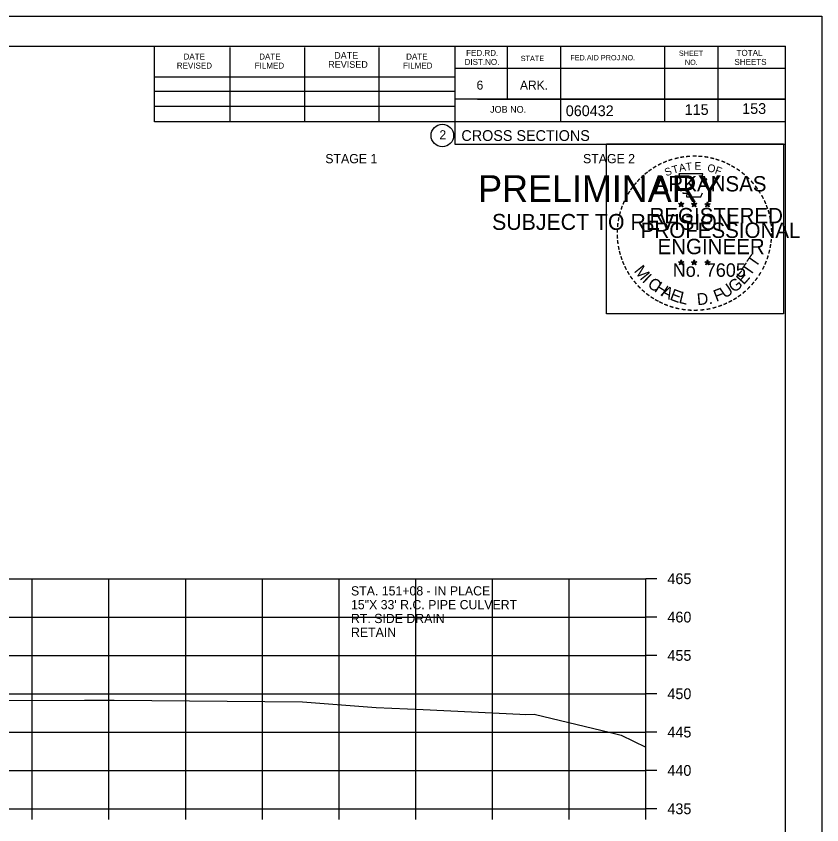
# Model space of a CAD drawing. Extents: x 1538688 to 1540766, y 656250 to 671912.
# Drawn here: x 1538916.1 to 1539021.1, y 664979.3 to 665084.8 of the extents above; entities that cross this region are included whole.
import ezdxf

# ---------------------------------------------------------------- set-up
doc = ezdxf.new("R2010")
doc.units = 0
for name, color, linetype in [('18', 7, 'Continuous'), ('22', 7, 'Continuous'), ('26', 7, 'Continuous'), ('7', 7, 'Continuous'), ('8', 7, 'Continuous'), ('9', 7, 'Continuous'), ('Borings', 7, 'Continuous'), ('Default', 7, 'Continuous'), ('Horizontal Alignment', 7, 'Continuous'), ('RipRap', 7, 'Continuous')]:
    doc.layers.add(name, color=color, linetype=linetype)

msp = doc.modelspace()

# ---------------------------------------------------------------- linework, layer by layer
at = {"layer": '18'}
msp.add_lwpolyline([(1538910.99, 664995.54), (1538924.98, 664995.57), (1538927.5, 664995.56), (1538928.54, 664995.55), (1538928.86, 664995.55), (1538953.39, 664995.37), (1538962.99, 664994.59), (1538969.15, 664994.37), (1538981.75, 664993.74), (1538982.53, 664993.71), (1538983.63, 664993.72), (1538993.58, 664991.37), (1538994.96, 664991.02), (1538998.18, 664989.45)], dxfattribs=at)
at = {"layer": '22'}
for p, q in [((1538718.18, 665011.4), (1538998.18, 665011.4)), ((1538918.18, 664981.4), (1538918.18, 665011.4)), ((1538928.18, 664981.4), (1538928.18, 665011.4)), ((1538938.18, 664981.4), (1538938.18, 665011.4)), ((1538948.18, 664981.4), (1538948.18, 665011.4)), ((1538958.18, 664981.4), (1538958.18, 665011.4)), ((1538968.18, 664981.4), (1538968.18, 665011.4)), ((1538978.18, 664981.4), (1538978.18, 665011.4)), ((1538988.18, 664981.4), (1538988.18, 665011.4)), ((1538998.18, 664981.4), (1538998.18, 665011.4)), ((1538718.18, 665006.4), (1538998.18, 665006.4)), ((1538718.18, 665001.4), (1538998.18, 665001.4)), ((1538718.18, 664996.4), (1538998.18, 664996.4)), ((1538718.18, 664991.4), (1538998.18, 664991.4)), ((1538718.18, 664986.4), (1538998.18, 664986.4)), ((1538718.18, 664981.4), (1538998.18, 664981.4))]:
    msp.add_line(p, q, dxfattribs=at)
at = {"layer": '26'}
msp.add_line((1538687.78, 665084.75), (1539021.11, 665084.75), dxfattribs=at)
for points in [[(1538687.77, 665084.75), (1539021.11, 665084.75), (1539021.11, 664871.42), (1538687.77, 664871.42)], [(1538993.03, 665068.09), (1539016.13, 665068.09), (1539016.13, 665045.94), (1538993.03, 665045.94)]]:
    msp.add_lwpolyline(points, close=True, dxfattribs=at)
at = {"layer": '8'}
for p, q in [((1539002.44, 665060.31), (1539002.79, 665060.2)), ((1539002.44, 665060.31), (1539002.69, 665060.26)), ((1539002.44, 665060.31), (1539002.68, 665060.18)), ((1539002.57, 665059.9), (1539002.79, 665060.2)), ((1539002.57, 665059.9), (1539002.7, 665060.14)), ((1539002.57, 665059.9), (1539002.79, 665060.12)), ((1539002.79, 665060.56), (1539002.75, 665060.31)), ((1539002.79, 665060.2), (1539002.79, 665060.56)), ((1539002.79, 665060.56), (1539002.84, 665060.31)), ((1539003.13, 665060.31), (1539002.79, 665060.2)), ((1539003, 665059.9), (1539002.79, 665060.2)), ((1539003, 665059.9), (1539002.79, 665060.11)), ((1539003.13, 665060.31), (1539002.85, 665060.26)), ((1539003, 665059.9), (1539002.86, 665060.19)), ((1539003.13, 665060.31), (1539002.93, 665060.2)), ((1539004.11, 665060.31), (1539004.46, 665060.2)), ((1539004.11, 665060.31), (1539004.36, 665060.26)), ((1539004.11, 665060.31), (1539004.35, 665060.18)), ((1539004.24, 665059.9), (1539004.46, 665060.2)), ((1539004.24, 665059.9), (1539004.37, 665060.14)), ((1539004.24, 665059.9), (1539004.46, 665060.12)), ((1539004.46, 665060.56), (1539004.42, 665060.31)), ((1539004.46, 665060.2), (1539004.46, 665060.56)), ((1539004.46, 665060.56), (1539004.51, 665060.31)), ((1539004.8, 665060.31), (1539004.46, 665060.2)), ((1539004.67, 665059.9), (1539004.46, 665060.2)), ((1539004.67, 665059.9), (1539004.46, 665060.11)), ((1539004.8, 665060.31), (1539004.52, 665060.26)), ((1539004.67, 665059.9), (1539004.53, 665060.19)), ((1539004.8, 665060.31), (1539004.6, 665060.2)), ((1539005.87, 665060.29), (1539006.22, 665060.18)), ((1539005.87, 665060.29), (1539006.13, 665060.25)), ((1539005.87, 665060.29), (1539006.11, 665060.17)), ((1539006.01, 665059.89), (1539006.22, 665060.18)), ((1539006.01, 665059.89), (1539006.13, 665060.13)), ((1539006.01, 665059.89), (1539006.22, 665060.1)), ((1539006.22, 665060.55), (1539006.18, 665060.3)), ((1539006.22, 665060.18), (1539006.22, 665060.55)), ((1539006.22, 665060.55), (1539006.27, 665060.3)), ((1539006.57, 665060.29), (1539006.22, 665060.18)), ((1539006.43, 665059.89), (1539006.22, 665060.18)), ((1539006.43, 665059.89), (1539006.22, 665060.1)), ((1539006.57, 665060.29), (1539006.28, 665060.25)), ((1539006.43, 665059.89), (1539006.3, 665060.18)), ((1539006.57, 665060.29), (1539006.36, 665060.19)), ((1539002.43, 665052.73), (1539002.78, 665052.62)), ((1539002.43, 665052.73), (1539002.69, 665052.69)), ((1539002.43, 665052.73), (1539002.67, 665052.61)), ((1539002.57, 665052.33), (1539002.78, 665052.62)), ((1539002.57, 665052.33), (1539002.69, 665052.57)), ((1539002.78, 665052.99), (1539002.74, 665052.74)), ((1539002.78, 665052.62), (1539002.78, 665052.99)), ((1539002.78, 665052.99), (1539002.83, 665052.74)), ((1539003.13, 665052.73), (1539002.78, 665052.62)), ((1539003, 665052.33), (1539002.78, 665052.62)), ((1539003.13, 665052.73), (1539002.84, 665052.68)), ((1539003, 665052.33), (1539002.86, 665052.62)), ((1539003.13, 665052.73), (1539002.93, 665052.63)), ((1539004.1, 665052.73), (1539004.45, 665052.62)), ((1539004.1, 665052.73), (1539004.36, 665052.69)), ((1539004.1, 665052.73), (1539004.34, 665052.61)), ((1539004.24, 665052.33), (1539004.45, 665052.62)), ((1539004.24, 665052.33), (1539004.36, 665052.57)), ((1539004.45, 665052.99), (1539004.41, 665052.74)), ((1539004.45, 665052.62), (1539004.45, 665052.99)), ((1539004.45, 665052.99), (1539004.5, 665052.74)), ((1539004.8, 665052.73), (1539004.45, 665052.62)), ((1539004.67, 665052.33), (1539004.45, 665052.62)), ((1539004.8, 665052.73), (1539004.51, 665052.68)), ((1539004.67, 665052.33), (1539004.53, 665052.62)), ((1539004.8, 665052.73), (1539004.6, 665052.63)), ((1539005.87, 665052.72), (1539006.22, 665052.61)), ((1539005.87, 665052.72), (1539006.12, 665052.68)), ((1539005.87, 665052.72), (1539006.11, 665052.6)), ((1539006, 665052.32), (1539006.22, 665052.61)), ((1539006, 665052.32), (1539006.13, 665052.56)), ((1539006.22, 665052.98), (1539006.18, 665052.73)), ((1539006.22, 665052.61), (1539006.22, 665052.98)), ((1539006.22, 665052.98), (1539006.27, 665052.73)), ((1539006.57, 665052.72), (1539006.22, 665052.61)), ((1539006.43, 665052.32), (1539006.22, 665052.61)), ((1539006.57, 665052.72), (1539006.28, 665052.67)), ((1539006.43, 665052.32), (1539006.3, 665052.61)), ((1539006.57, 665052.72), (1539006.36, 665052.62)), ((1539002.57, 665052.33), (1539002.78, 665052.54)), ((1539003, 665052.33), (1539002.78, 665052.54)), ((1539004.24, 665052.33), (1539004.45, 665052.54)), ((1539004.67, 665052.33), (1539004.45, 665052.54)), ((1539006, 665052.32), (1539006.22, 665052.53)), ((1539006.43, 665052.32), (1539006.22, 665052.53))]:
    msp.add_line(p, q, dxfattribs=at)
for points in [[(1539002.48, 665064.18), (1539002.75, 665063.36)], [(1539005.99, 665063.26), (1539006.13, 665063.55), (1539005.45, 665063.52), (1539005.6, 665064.18), (1539002.48, 665064.18)], [(1539002.97, 665061.76), (1539002.97, 665061.67), (1539003.53, 665061.66), (1539003.48, 665061.18), (1539005.35, 665061.18), (1539005.55, 665061.72)], [(1539002.79, 665060.56), (1539003, 665059.9), (1539002.44, 665060.31), (1539003.13, 665060.31), (1539002.57, 665059.9), (1539002.79, 665060.56)], [(1539004.46, 665060.56), (1539004.67, 665059.9), (1539004.11, 665060.31), (1539004.8, 665060.31), (1539004.24, 665059.9), (1539004.46, 665060.56)], [(1539006.22, 665060.55), (1539006.43, 665059.89), (1539005.87, 665060.29), (1539006.57, 665060.29), (1539006.01, 665059.89), (1539006.22, 665060.55)], [(1539002.78, 665052.99), (1539003, 665052.33), (1539002.43, 665052.73), (1539003.13, 665052.73), (1539002.57, 665052.33), (1539002.78, 665052.99)], [(1539004.45, 665052.99), (1539004.67, 665052.33), (1539004.1, 665052.73), (1539004.8, 665052.73), (1539004.24, 665052.33), (1539004.45, 665052.99)], [(1539006.22, 665052.98), (1539006.43, 665052.32), (1539005.87, 665052.72), (1539006.57, 665052.72), (1539006, 665052.32), (1539006.22, 665052.98)]]:
    msp.add_lwpolyline(points, dxfattribs=at)
for centre, radius in [((1539002.79, 665060.2), 0.172), ((1539002.79, 665060.2), 0.145), ((1539002.79, 665060.2), 0.116), ((1539002.79, 665060.2), 0.0991), ((1539002.79, 665060.2), 0.0747), ((1539002.79, 665060.2), 0.0495), ((1539002.79, 665060.2), 0.0296), ((1539004.46, 665060.2), 0.172), ((1539004.46, 665060.2), 0.145), ((1539004.46, 665060.2), 0.116), ((1539004.46, 665060.2), 0.0991), ((1539004.46, 665060.2), 0.0747), ((1539004.46, 665060.2), 0.0495), ((1539004.46, 665060.2), 0.0296), ((1539006.22, 665060.18), 0.172), ((1539006.22, 665060.18), 0.145), ((1539006.22, 665060.18), 0.116), ((1539006.22, 665060.18), 0.0991), ((1539006.22, 665060.18), 0.0747), ((1539006.22, 665060.18), 0.0495), ((1539006.22, 665060.18), 0.0296), ((1539002.78, 665052.62), 0.172), ((1539002.78, 665052.62), 0.145), ((1539002.78, 665052.62), 0.116), ((1539002.78, 665052.62), 0.0991), ((1539002.78, 665052.62), 0.0747), ((1539002.78, 665052.62), 0.0495), ((1539002.78, 665052.62), 0.0296), ((1539004.45, 665052.62), 0.172), ((1539004.45, 665052.62), 0.145), ((1539004.45, 665052.62), 0.116), ((1539004.45, 665052.62), 0.0991), ((1539004.45, 665052.62), 0.0747), ((1539004.45, 665052.62), 0.0495), ((1539004.45, 665052.62), 0.0296), ((1539006.22, 665052.61), 0.172), ((1539006.22, 665052.61), 0.145), ((1539006.22, 665052.61), 0.116), ((1539006.22, 665052.61), 0.0991), ((1539006.22, 665052.61), 0.0747), ((1539006.22, 665052.61), 0.0495), ((1539006.22, 665052.61), 0.0296)]:
    msp.add_circle(centre, radius, dxfattribs=at)
at = {"layer": 'Borings'}
for p, q in [((1538998.18, 664981.4), (1538998.18, 665011.4)), ((1538999.58, 665011.4), (1538998.18, 665011.4)), ((1538999.58, 665006.4), (1538998.18, 665006.4)), ((1538999.58, 665001.4), (1538998.18, 665001.4)), ((1538999.58, 664996.4), (1538998.18, 664996.4)), ((1538999.58, 664991.4), (1538998.18, 664991.4)), ((1538999.58, 664986.4), (1538998.18, 664986.4)), ((1538718.18, 664981.4), (1538998.18, 664981.4)), ((1538918.18, 664980), (1538918.18, 664981.4)), ((1538928.18, 664980), (1538928.18, 664981.4)), ((1538938.18, 664980), (1538938.18, 664981.4)), ((1538948.18, 664980), (1538948.18, 664981.4)), ((1538958.18, 664980), (1538958.18, 664981.4)), ((1538968.18, 664980), (1538968.18, 664981.4)), ((1538978.18, 664980), (1538978.18, 664981.4)), ((1538988.18, 664980), (1538988.18, 664981.4)), ((1538998.18, 664980), (1538998.18, 664981.4)), ((1538999.58, 664981.4), (1538998.18, 664981.4))]:
    msp.add_line(p, q, dxfattribs=at)
at = {"layer": 'RipRap'}
for p, q in [((1538700.18, 665080.86), (1539016.36, 665080.86)), ((1538934.1, 665070.98), (1538934.1, 665080.86)), ((1538943.96, 665070.98), (1538943.96, 665080.66)), ((1538953.72, 665070.98), (1538953.72, 665080.66)), ((1538963.4, 665070.98), (1538963.4, 665080.66)), ((1538973.26, 665080.86), (1538973.26, 665068.06)), ((1538980.1, 665080.86), (1538980.1, 665073.92)), ((1538987.04, 665080.86), (1538987.04, 665070.98)), ((1539000.62, 665080.86), (1539000.62, 665070.98)), ((1539007.56, 665080.86), (1539007.56, 665070.98)), ((1539016.36, 664875.4), (1539016.36, 665080.86)), ((1539016.36, 665077.92), (1538973.26, 665077.92)), ((1539016.36, 665077.94), (1539016.36, 665077.94)), ((1538934.1, 665076.84), (1538973.26, 665076.84)), ((1538934.1, 665074.98), (1538973.26, 665074.98)), ((1539016.36, 665073.92), (1538973.26, 665073.92)), ((1538976.22, 665073.92), (1539016.36, 665073.92)), ((1538934.1, 665070.98), (1538934.1, 665073.04)), ((1538934.1, 665073.04), (1538973.26, 665073.04)), ((1539016.36, 665070.98), (1538934.1, 665070.98)), ((1538973.26, 665068.06), (1539016.36, 665068.06))]:
    msp.add_line(p, q, dxfattribs=at)
msp.add_circle((1538971.64, 665069.2), 1.47, dxfattribs=at)

# ---------------------------------------------------------------- texts
at = {"layer": '7'}
for s, p in [('115', (1539003.23, 665071.88)), ('153', (1539010.73, 665072.01))]:
    msp.add_text(s, height=1.4, dxfattribs=at).set_placement(p)
at = {"layer": '8'}
for s, height, rotation, p in [('-', 1.6, 13.6301, (1539001.98, 665065.55)), ('-', 1.6, 10.2193, (1539002.66, 665065.71)), ('-', 1.6, 5.8968, (1539003.38, 665065.82)), ('-', 1.6, 0.1862, (1539004.16, 665065.9)), ('-', 1.6, 357.743, (1539004.88, 665065.88)), ('-', 1.6, 352.1617, (1539005.62, 665065.83)), ('-', 1.6, 347.2049, (1539006.34, 665065.71)), ('-', 1.6, 34.0636, (1538999.36, 665064.36)), ('-', 1.6, 28.7918, (1538999.96, 665064.73)), ('-', 1.6, 24.3072, (1539000.59, 665065.04)), ('-', 1.6, 19.1761, (1539001.23, 665065.31)), ('T', 1, 16.4036, (1539001.75, 665064.19)), ('A', 1, 11.2132, (1539002.57, 665064.44)), ('T', 1, 6.0228, (1539003.42, 665064.61)), ('E', 1, 0.8323, (1539004.53, 665064.72)), ('O', 1, 350.4515, (1539006.13, 665064.51)), ('-', 1.6, 342.3362, (1539006.98, 665065.56)), ('-', 1.6, 337.8551, (1539007.71, 665065.34)), ('-', 1.6, 334.1211, (1539008.34, 665065.06)), ('-', 1.6, 329.6409, (1539008.92, 665064.78)), ('-', 1.6, 38.9507, (1538998.31, 665063.58)), ('-', 1.6, 36.2317, (1538998.79, 665063.96)), ('S', 1, 21.594, (1539000.83, 665063.86)), ('F', 1, 340.0707, (1539007.09, 665064.28)), ('-', 1.6, 325.8627, (1539009.57, 665064.42)), ('-', 1.6, 320.5297, (1539010.18, 665063.99)), ('-', 1.6, 50.6142, (1538997.03, 665062.2)), ('-', 1.6, 48.423, (1538997.43, 665062.69)), ('-', 1.6, 42.9622, (1538997.88, 665063.17)), ('ARKANSAS', 2, 360, (1538999.33, 665061.9)), ('-', 1.6, 315.5786, (1539010.77, 665063.51)), ('-', 1.6, 309.8797, (1539011.34, 665062.96)), ('-', 1.6, 54.2325, (1538996.61, 665061.63)), ('-', 1.6, 306.6522, (1539011.87, 665062.35)), ('-', 1.4, 303.6753, (1539012.35, 665061.79)), ('-', 1.6, 62.8713, (1538995.97, 665060.49)), ('-', 1.6, 58.0706, (1538996.29, 665061.11)), ('-', 1.6, 299.6684, (1539012.67, 665061.18)), ('-', 1.6, 72.3945, (1538995.5, 665059.25)), ('-', 1.6, 67.7743, (1538995.72, 665059.88)), ('DWB', 0.01, 360, (1539002.77, 665060.19)), ('DWB', 0.01, 360, (1539004.44, 665060.19)), ('DWB', 0.01, 360, (1539006.21, 665060.18)), ('-', 1.6, 294.6628, (1539013, 665060.57)), ('-', 1.6, 290.5728, (1539013.25, 665059.99)), ('-', 1.6, 75.461, (1538995.3, 665058.54)), ('REGISTERED', 2, 360, (1538998.65, 665057.75)), ('-', 1.6, 285.1233, (1539013.49, 665059.41)), ('-', 1.6, 81.2013, (1538995.17, 665057.83)), ('PROFESSIONAL', 2, 360, (1538997.51, 665055.84)), ('-', 1.6, 280.5493, (1539013.69, 665058.67)), ('-', 1.6, 276.5962, (1539013.85, 665057.9)), ('-', 1.6, 89.0622, (1538995.07, 665056.43)), ('-', 1.6, 85.1863, (1538995.09, 665057.13)), ('-', 1.6, 274.3301, (1539013.91, 665057.18)), ('-', 1.6, 94.1959, (1538995.1, 665055.71)), ('ENGINEER', 2, 360, (1538999.69, 665053.72)), ('-', 1.6, 263.5172, (1539013.93, 665055.88)), ('-', 1.6, 269.9407, (1539013.94, 665056.55)), ('-', 1.6, 98.9479, (1538995.17, 665055.04)), ('-', 1.6, 101.7149, (1538995.31, 665054.31)), ('-', 1.6, 260.9953, (1539013.85, 665055.23)), ('-', 1.6, 105.4578, (1538995.47, 665053.71)), ('T', 1.54, 55.055, (1539012.5, 665051.89)), ('-', 1.6, 255.7626, (1539013.74, 665054.55)), ('-', 1.6, 109.0874, (1538995.69, 665053.08)), ('-', 1.6, 114.0643, (1538995.94, 665052.49)), ('No. 7605', 1.757, 360, (1539001.67, 665050.77)), ('DWB', 0.01, 360, (1539002.77, 665052.62)), ('DWB', 0.01, 360, (1539004.44, 665052.62)), ('DWB', 0.01, 360, (1539006.2, 665052.61)), ('T', 1.54, 55.055, (1539011.77, 665050.77)), ('-', 1.6, 247.8887, (1539013.34, 665053.16)), ('-', 1.6, 252.8681, (1539013.56, 665053.83)), ('-', 1.6, 115.7289, (1538996.24, 665051.87)), ('-', 1.6, 120.4471, (1538996.6, 665051.28)), ('M', 1.54, 308.9175, (1538996.55, 665051.51)), ('E', 1.54, 48.7313, (1539010.93, 665049.64)), ('-', 1.6, 244.6197, (1539013.08, 665052.53)), ('-', 1.6, 125.8934, (1538997, 665050.72)), ('I', 1.54, 316.4636, (1538997.6, 665050.19)), ('C', 1.54, 324.0197, (1538998.27, 665049.57)), ('G', 1.54, 38.2173, (1539009.67, 665048.62)), ('-', 1.6, 233.8452, (1539012.28, 665051.12)), ('-', 1.6, 239.0712, (1539012.68, 665051.77)), ('-', 1.6, 130.7181, (1538997.47, 665050.17)), ('-', 1.6, 134.2238, (1538997.98, 665049.62)), ('H', 1.54, 327.5342, (1538999.18, 665048.92)), ('A', 1.54, 332.5513, (1539000.03, 665048.38)), ('U', 1.54, 34.4052, (1539008.47, 665047.89)), ('-', 1.6, 225.7653, (1539011.37, 665049.99)), ('-', 1.6, 231.2538, (1539011.85, 665050.56)), ('-', 1.6, 138.9338, (1538998.51, 665049.16)), ('-', 1.6, 144.6463, (1538999.06, 665048.75)), ('E', 1.54, 339.2068, (1539001.19, 665047.82)), ('L', 1.54, 346.2929, (1539002.38, 665047.39)), ('D.', 1.54, 5.2602, (1539004.89, 665047.06)), ('F', 1.54, 20.8202, (1539007.34, 665047.49)), ('-', 1.6, 215.7363, (1539010.3, 665049.01)), ('-', 1.6, 221.0851, (1539010.85, 665049.48)), ('-', 1.6, 148.0898, (1538999.63, 665048.38)), ('-', 1.6, 151.5704, (1539000.2, 665048.06)), ('-', 1.6, 154.6002, (1539000.73, 665047.81)), ('-', 1.6, 158.5612, (1539001.35, 665047.56)), ('-', 1.6, 204.2516, (1539008.59, 665047.96)), ('-', 1.6, 207.3568, (1539009.21, 665048.28)), ('-', 1.6, 212.2491, (1539009.77, 665048.62)), ('-', 1.6, 162.7983, (1539002.04, 665047.34)), ('-', 1.6, 167.5555, (1539002.75, 665047.18)), ('-', 1.6, 173.1155, (1539003.52, 665047.07)), ('-', 1.6, 176.5183, (1539004.27, 665047.02)), ('-', 1.6, 181.5918, (1539005.02, 665047.04)), ('-', 1.6, 185.8167, (1539005.83, 665047.11)), ('-', 1.6, 191.2858, (1539006.56, 665047.24)), ('-', 1.6, 195.4743, (1539007.29, 665047.44)), ('-', 1.6, 200.7184, (1539007.97, 665047.69))]:
    msp.add_text(s, height=height, rotation=rotation, dxfattribs=at).set_placement(p)
at = {"layer": '9'}
for s, height, p in [('PRELIMINARY', 3.5, (1538976.31, 665060.52)), ('DWB', 0.01, (1538977.06, 665062.37)), ('SUBJECT TO REVISION', 2.0751, (1538978.12, 665056.89))]:
    msp.add_text(s, height=height, rotation=360, dxfattribs=at).set_placement(p)
at = {"layer": 'Default'}
for s, p in [('STAGE 1', (1538956.38, 665065.58)), ('STAGE 2', (1538989.98, 665065.58)), ('STA. 151+08 - IN PLACE', (1538959.73, 665009.22)), ('15"X 33\' R.C. PIPE CULVERT', (1538959.73, 665007.42)), ('RT. SIDE DRAIN', (1538959.73, 665005.62)), ('RETAIN', (1538959.73, 665003.82))]:
    msp.add_text(s, height=1.2, dxfattribs=at).set_placement(p)
at = {"layer": 'Horizontal Alignment'}
for s, p in [('465', (1539000.98, 665010.7)), ('460', (1539000.98, 665005.7)), ('455', (1539000.98, 665000.7)), ('450', (1539000.98, 664995.7)), ('445', (1539000.98, 664990.7)), ('440', (1539000.98, 664985.7)), ('435', (1539000.98, 664980.7))]:
    msp.add_text(s, height=1.4, dxfattribs=at).set_placement(p)
at = {"layer": 'RipRap'}
for s, height, p in [('DATE', 0.879, (1538957.54, 665079.2)), ('FED.RD.', 0.782, (1538974.74, 665079.58)), ('SHEET', 0.684, (1539002.48, 665079.58)), ('TOTAL', 0.782, (1539010, 665079.58)), ('DATE', 0.782, (1538937.9, 665079.1)), ('DATE', 0.782, (1538947.76, 665079.1)), ('REVISED', 0.879, (1538956.76, 665078.02)), ('DATE', 0.782, (1538966.92, 665079.1)), ('DIST.NO.', 0.782, (1538974.54, 665078.4)), ('STATE', 0.684, (1538981.86, 665078.9)), ('FED.AID PROJ.NO.', 0.684, (1538988.32, 665079)), ('NO.', 0.684, (1539003.26, 665078.4)), ('SHEETS', 0.782, (1539009.72, 665078.4)), ('REVISED', 0.782, (1538937.02, 665077.92)), ('FILMED', 0.782, (1538947.18, 665077.92)), ('FILMED', 0.782, (1538966.52, 665077.92)), ('6', 1.17, (1538976.1, 665075.18)), ('ARK.', 1.172, (1538981.76, 665075.18)), ('JOB NO.', 0.879, (1538977.86, 665072.16)), ('060432', 1.4, (1538987.73, 665071.72)), ('2', 1.17, (1538971.26, 665068.71)), ('CROSS SECTIONS', 1.4, (1538974.12, 665068.49))]:
    msp.add_text(s, height=height, rotation=360, dxfattribs=at).set_placement(p)

doc.saveas('drawing.dxf')
